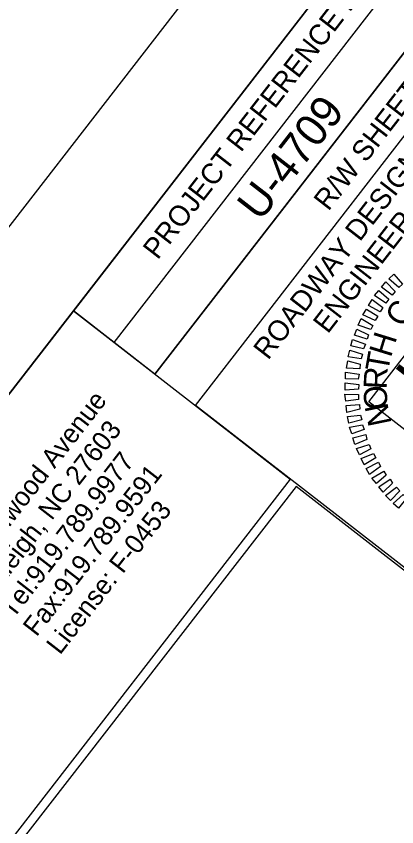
# Model space of a CAD drawing. Extents: x 2013373 to 2015284, y 444618 to 446636.
# Drawn here: x 2014282.4 to 2014375, y 446317 to 446513.9 of the extents above; entities that cross this region are included whole.
import ezdxf

# ---------------------------------------------------------------- set-up
doc = ezdxf.new("R2010")
doc.units = 0
for name, color, linetype in [('Old_Level_15', 7, 'Continuous'), ('Prop Conc 1ft 6in Curb and Gutter', 7, 'Continuous'), ('Prop Conc 5in Monolithic Keyed In Island', 7, 'Continuous'), ('Prop Dimension', 7, 'Continuous'), ('Prop Horizontal Alignment', 7, 'Continuous'), ('Prop Horizontal Alignment Tick Large', 7, 'Continuous'), ('Prop Noise Wall', 7, 'Continuous'), ('Prop ROW Station Offsets', 7, 'Continuous')]:
    doc.layers.add(name, color=color, linetype=linetype)

msp = doc.modelspace()

# ---------------------------------------------------------------- linework, layer by layer
at = {"layer": 'Old_Level_15'}
for points in [[(2014375.45, 446448), (2014373, 446450.15), (2014374.25, 446451.27), (2014376.34, 446448.83)], [(2014373.8, 446446.12), (2014371.23, 446448.11), (2014372.28, 446449.38), (2014374.57, 446447.03)], [(2014372.29, 446444.25), (2014369.57, 446446.04), (2014370.62, 446447.32), (2014373.06, 446445.17)], [(2014370.95, 446442.12), (2014368.09, 446443.65), (2014368.97, 446445.11), (2014371.57, 446443.16)], [(2014369.72, 446440.04), (2014366.7, 446441.37), (2014367.59, 446442.77), (2014370.34, 446441.08)], [(2014368.68, 446437.81), (2014365.55, 446438.91), (2014366.32, 446440.47), (2014369.13, 446438.79)], [(2014367.73, 446435.51), (2014364.65, 446436.44), (2014365.25, 446437.94), (2014368.09, 446436.56)], [(2014366.86, 446433.09), (2014363.77, 446433.84), (2014364.22, 446435.39), (2014367.39, 446434.26)], [(2014366.34, 446430.7), (2014363.15, 446431.16), (2014363.54, 446432.81), (2014366.66, 446431.85)], [(2014365.97, 446428.27), (2014362.7, 446428.46), (2014363.02, 446430.18), (2014366.08, 446429.39)], [(2014365.61, 446425.77), (2014362.46, 446425.87), (2014362.51, 446427.48), (2014365.81, 446427)], [(2014365.63, 446423.34), (2014362.42, 446423.12), (2014362.41, 446424.83), (2014365.7, 446424.49)], [(2014365.63, 446420.81), (2014362.54, 446420.42), (2014362.33, 446422.11), (2014365.66, 446421.99)], [(2014366, 446418.44), (2014362.82, 446417.68), (2014362.68, 446419.37), (2014365.86, 446419.56)], [(2014366.43, 446415.89), (2014363.3, 446415.03), (2014362.94, 446416.7), (2014366.15, 446417)], [(2014367.01, 446413.54), (2014364.01, 446412.45), (2014363.45, 446414.09), (2014366.66, 446414.64)], [(2014367.67, 446411.13), (2014364.77, 446409.84), (2014364.28, 446411.49), (2014367.45, 446412.31)], [(2014368.64, 446408.86), (2014365.9, 446407.38), (2014365.14, 446408.92), (2014368.25, 446409.92)], [(2014369.84, 446406.66), (2014367.03, 446404.92), (2014366.27, 446406.46), (2014369.28, 446407.73)], [(2014370.97, 446404.53), (2014368.36, 446402.63), (2014367.53, 446404.09), (2014370.48, 446405.6)], [(2014372.4, 446402.46), (2014369.99, 446400.41), (2014368.9, 446401.7), (2014371.82, 446403.42)], [(2014373.9, 446400.48), (2014371.69, 446398.27), (2014370.56, 446399.59), (2014373.32, 446401.44)], [(2014375.67, 446398.6), (2014373.47, 446396.25), (2014372.25, 446397.45), (2014374.88, 446399.53)], [(2014377.42, 446396.93), (2014375.35, 446394.42), (2014374.1, 446395.51), (2014376.53, 446397.75)]]:
    msp.add_lwpolyline(points, close=True, dxfattribs=at)
at = {"layer": 'Prop Conc 5in Monolithic Keyed In Island'}
msp.add_lwpolyline([(2014241.91, 444618.03), (2015283.73, 445961.39), (2014414.5, 446635.51), (2013372.67, 445292.15)], close=True, dxfattribs=at)
at = {"layer": 'Prop Dimension'}
msp.add_lwpolyline([(2014173.74, 446284.27), (2014296.33, 446442.35), (2014349.03, 446401.48), (2014226.44, 446243.4)], close=True, dxfattribs=at)
at = {"layer": 'Prop Horizontal Alignment'}
for p, q in [((2014306.25, 446434.66), (2014428.85, 446592.74)), ((2014316.13, 446427), (2014438.73, 446585.08))]:
    msp.add_line(p, q, dxfattribs=at)
for points in [[(2014418.93, 446600.43), (2013499.68, 445415.12), (2014329.4, 444771.64), (2015248.65, 445956.96)], [(2014296.33, 446442.35), (2014418.93, 446600.43), (2014438.73, 446585.08), (2014316.13, 446427)], [(2014326.01, 446419.34), (2014387.32, 446498.4), (2014476.22, 446429.46), (2014414.9, 446350.4)]]:
    msp.add_lwpolyline(points, close=True, dxfattribs=at)
at = {"layer": 'Prop Horizontal Alignment Tick Large'}
msp.add_lwpolyline([(2014386.73, 446405.85), (2014368.16, 446420.25), (2014458.24, 446536.41), (2014476.81, 446522.01)], close=True, dxfattribs=at)
at = {"layer": 'Prop Noise Wall'}
msp.add_lwpolyline([(2014144.54, 446243.36), (2013513.08, 445427.57), (2013603.78, 445375.37), (2013612.37, 445329.9), (2013915.76, 445258.44), (2014041.96, 445083.42), (2014361.11, 444814.86), (2015247.36, 445957.62), (2014564.18, 446487.45), (2014441.6, 446328.92), (2014350.52, 446399.67), (2014197.18, 446202.42)], close=True, dxfattribs=at)

# ---------------------------------------------------------------- texts
at = {"layer": 'Old_Level_15'}
for s, rotation, p in [('C', 58.425, (2014376.6, 446438.06)), ('H', 72.8246, (2014373.52, 446430.83)), ('T', 80.0249, (2014372.83, 446427.25)), ('R', 87.2256, (2014372.49, 446423.21)), ('O', 94.4268, (2014372.83, 446418.59)), ('N', 101.6286, (2014373.71, 446414.99))]:
    msp.add_text(s, height=5.64, rotation=rotation, dxfattribs=at).set_placement(p)
at = {"layer": 'Prop Conc 1ft 6in Curb and Gutter'}
msp.add_text('U-4709', height=7.75, rotation=52.2051, dxfattribs=at).set_placement((2014341.73, 446463.84))
at = {"layer": 'Prop Horizontal Alignment'}
for s, height, p in [('PROJECT REFERENCE NO.', 5.0001, (2014316.81, 446454.56)), ('R/W SHEET NO.', 5.0001, (2014358.33, 446466.4)), ('ROADWAY DESIGN', 5.0001, (2014343.66, 446430.2)), ('ENGINEER', 5, (2014358.18, 446436.59))]:
    msp.add_text(s, height=height, rotation=52.2051, dxfattribs=at).set_placement(p)
at = {"layer": 'Prop Horizontal Alignment Tick Large'}
msp.add_text('INCOMPLETE PLANS', height=11.52, rotation=52.2051, dxfattribs=at).set_placement((2014382.97, 446420.09))
at = {"layer": 'Prop ROW Station Offsets'}
for s, p in [('1 Glenwood Avenue', (2014270.31, 446376.22)), ('Raleigh, NC 27603', (2014276, 446371.81)), ('Tel:919.789.9977 ', (2014281.69, 446367.4)), ('Fax:919.789.9591', (2014287.37, 446362.99)), ('License: F-0453', (2014293.06, 446358.58))]:
    msp.add_text(s, height=4.6576, rotation=52.2051, dxfattribs=at).set_placement(p)

doc.saveas('drawing.dxf')
